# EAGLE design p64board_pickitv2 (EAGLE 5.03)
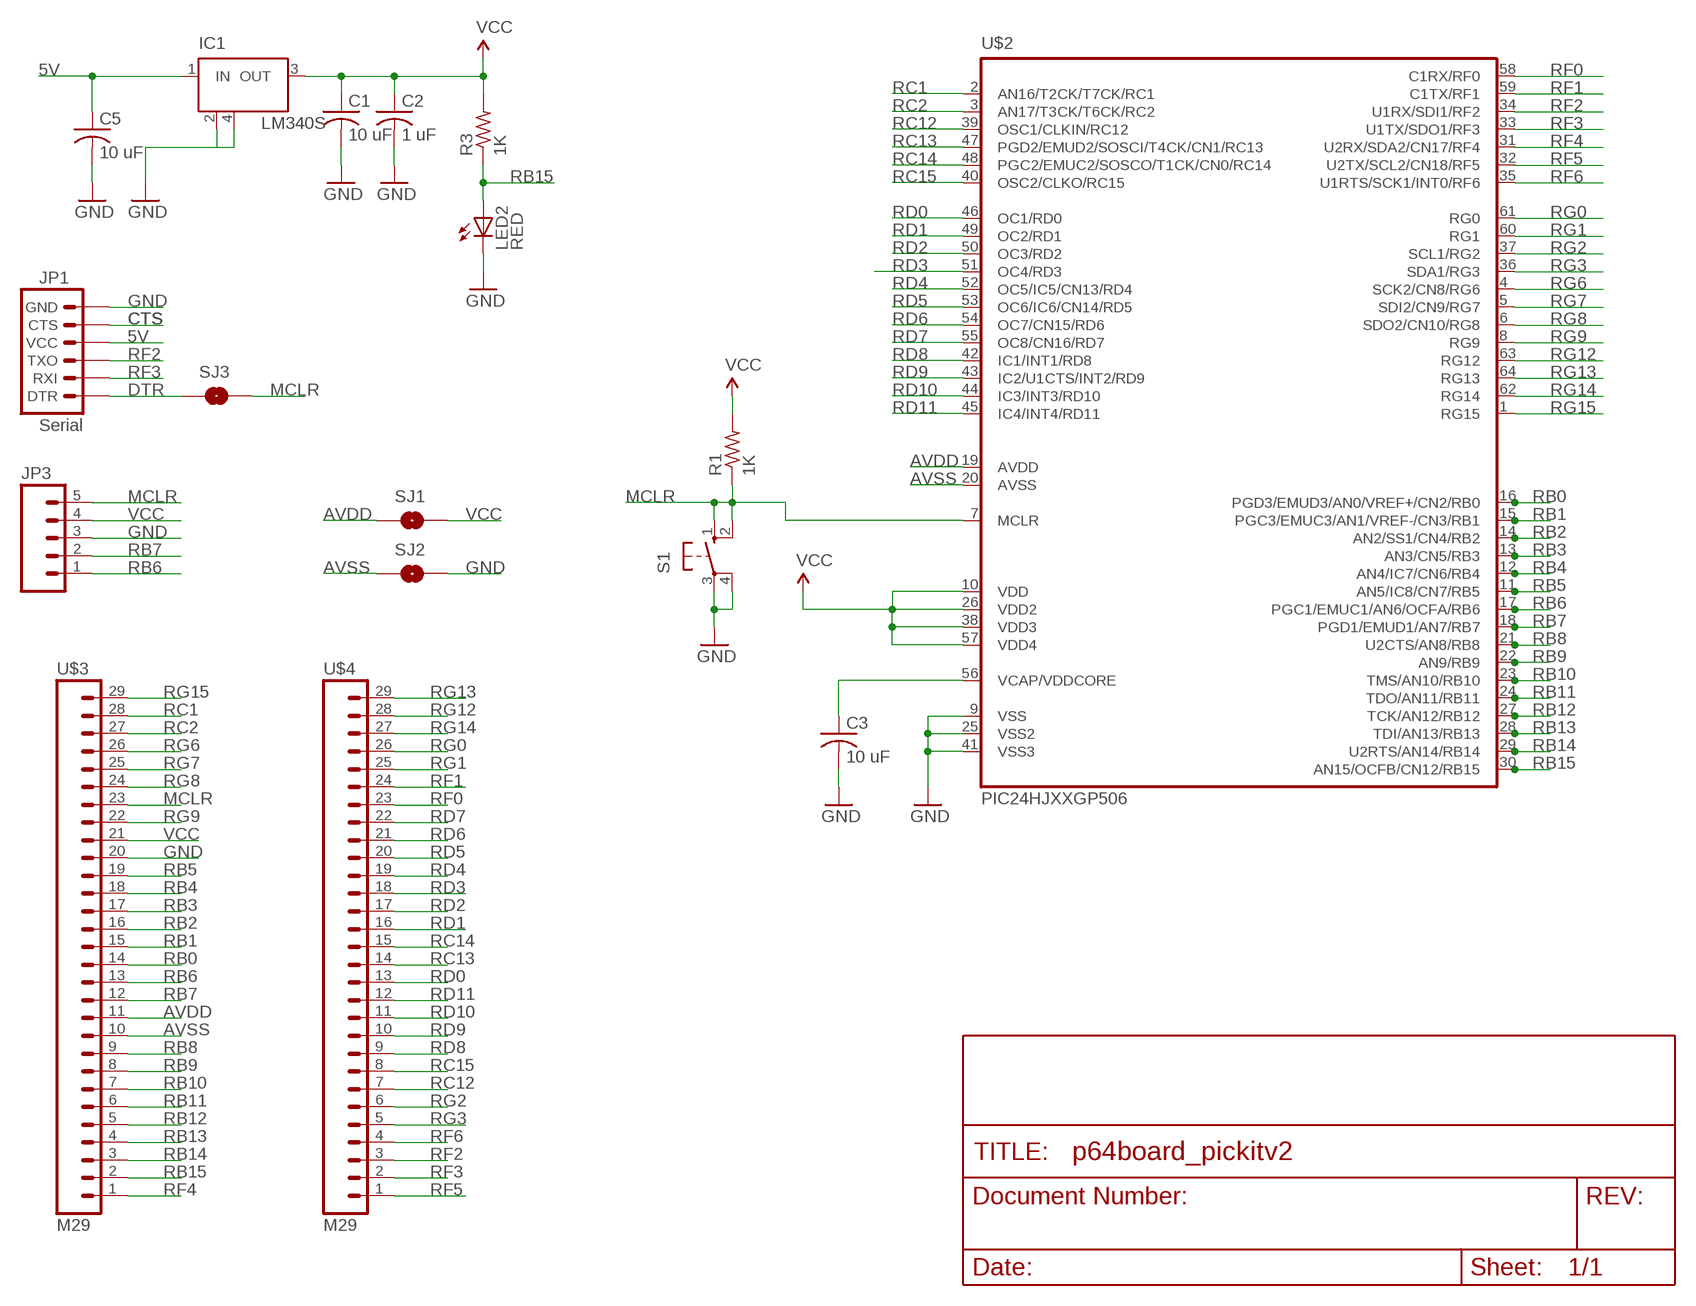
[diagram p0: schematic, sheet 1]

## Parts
C1  10 uF  C-US025-030X050  [C025-030X050]
C2  1 uF  C-US025-030X050  [C025-030X050]
C3  10 uF  C-US025-030X050  [C025-030X050]
C5  10 uF  C-US025-030X050  [C025-030X050]
IC1  LM340S  [SOT223]
JP1  Serial  ARDUINO_SERIAL_PROGRAMPTH  [1X06]
JP3  M05  [1X05]
LED2  RED  LED5MM  [LED5MM]
R1  1K  R-US_0204/7  [0204/7]
R3  1K  R-US_0204/7  [0204/7]
S1  10-XX  [B3F-10XX]
SJ1  Close  SOLDERJUMPERNC2  [SJ_2S]
SJ2  Close  SOLDERJUMPERNC2  [SJ_2S]
SJ3  Close  SOLDERJUMPERNC2  [SJ_2S]
U$2  PIC24HJXXGP506  [SQFP-S-10X10-64]
U$3  M29  [1X29]
U$4  M29  [1X29]

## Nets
5V: C5.1 IC1.1(IN) JP1.4(VCC)
AVDD: SJ1.1 U$3.11
AVSS: SJ2.1 U$3.10
CTS [vcc]: JP1.5(CTS)
DTR: JP1.1(DTR) SJ3.1
GND [vcc]: C1.2 C2.2 C3.2 C5.2 IC1.2(GND) IC1.4(GND) JP1.6(GND) JP3.3 LED2.K(C) S1.3(P) S1.4(P1) SJ2.2 U$2.9(VSS) U$2.25(VSS2) U$2.41(VSS3) U$3.20
MCLR: JP3.5 R1.1 S1.1(S) S1.2(S1) SJ3.2 U$2.7(MCLR) U$3.23
RB0: U$2.16(PGD3/EMUD3/AN0/VREF+/CN2/RB0) U$3.14
RB1: U$2.15(PGC3/EMUC3/AN1/VREF-/CN3/RB1) U$3.15
RB2: U$2.14(AN2/SS1/CN4/RB2) U$3.16
RB3: U$2.13(AN3/CN5/RB3) U$3.17
RB4: U$2.12(AN4/IC7/CN6/RB4) U$3.18
RB5: U$2.11(AN5/IC8/CN7/RB5) U$3.19
RB6: JP3.1 U$2.17(PGC1/EMUC1/AN6/OCFA/RB6) U$3.13
RB7: JP3.2 U$2.18(PGD1/EMUD1/AN7/RB7) U$3.12
RB8: U$2.21(U2CTS/AN8/RB8) U$3.9
RB9: U$2.22(AN9/RB9) U$3.8
RB10: U$2.23(TMS/AN10/RB10) U$3.7
RB11: U$2.24(TDO/AN11/RB11) U$3.6
RB12: U$2.27(TCK/AN12/RB12) U$3.5
RB13: U$2.28(TDI/AN13/RB13) U$3.4
RB14: U$2.29(U2RTS/AN14/RB14) U$3.3
RB15: LED2.A R3.1 U$2.30(AN15/OCFB/CN12/RB15) U$3.2
RC1: U$2.2(AN16/T2CK/T7CK/RC1) U$3.28
RC2: U$2.3(AN17/T3CK/T6CK/RC2) U$3.27
RC12: U$2.39(OSC1/CLKIN/RC12) U$4.7
RC13: U$2.47(PGD2/EMUD2/SOSCI/T4CK/CN1/RC13) U$4.14
RC14: U$2.48(PGC2/EMUC2/SOSCO/T1CK/CN0/RC14) U$4.15
RC15: U$2.40(OSC2/CLKO/RC15) U$4.8
RD0: U$2.46(OC1/RD0) U$4.13
RD1: U$2.49(OC2/RD1) U$4.16
RD2: U$2.50(OC3/RD2) U$4.17
RD3: U$2.51(OC4/RD3) U$4.18
RD4: U$2.52(OC5/IC5/CN13/RD4) U$4.19
RD5: U$2.53(OC6/IC6/CN14/RD5) U$4.20
RD6: U$2.54(OC7/CN15/RD6) U$4.21
RD7: U$2.55(OC8/CN16/RD7) U$4.22
RD8: U$2.42(IC1/INT1/RD8) U$4.9
RD9: U$2.43(IC2/U1CTS/INT2/RD9) U$4.10
RD10: U$2.44(IC3/INT3/RD10) U$4.11
RD11: U$2.45(IC4/INT4/RD11) U$4.12
RF0: U$2.58(C1RX/RF0) U$4.23
RF1: U$2.59(C1TX/RF1) U$4.24
RF2: JP1.3(TXO) U$2.34(U1RX/SDI1/RF2) U$4.3
RF3: JP1.2(RXI) U$2.33(U1TX/SDO1/RF3) U$4.2
RF4: U$2.31(U2RX/SDA2/CN17/RF4) U$3.1
RF5: U$2.32(U2TX/SCL2/CN18/RF5) U$4.1
RF6: U$2.35(U1RTS/SCK1/INT0/RF6) U$4.4
RG0: U$2.61(RG0) U$4.26
RG1: U$2.60(RG1) U$4.25
RG2: U$2.37(SCL1/RG2) U$4.6
RG3: U$2.36(SDA1/RG3) U$4.5
RG6: U$2.4(SCK2/CN8/RG6) U$3.26
RG7: U$2.5(SDI2/CN9/RG7) U$3.25
RG8: U$2.6(SDO2/CN10/RG8) U$3.24
RG9: U$2.8(RG9) U$3.22
RG12: U$2.63(RG12) U$4.28
RG13: U$2.64(RG13) U$4.29
RG14: U$2.62(RG14) U$4.27
RG15: U$2.1(RG15) U$3.29
VCAP: C3.1 U$2.56(VCAP/VDDCORE)
VCC: C1.1 C2.1 IC1.3(OUT) JP3.4 R1.2 R3.2 SJ1.2 U$2.10(VDD) U$2.26(VDD2) U$2.38(VDD3) U$2.57(VDD4) U$3.21

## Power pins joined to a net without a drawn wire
AVDD: U$2.19(AVDD)
AVSS: U$2.20(AVSS)

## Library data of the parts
C1-C3 C5 = rcl:C-US: CAPACITOR, American symbol
IC1 = linear:LM340S: 3-Terminal Positive Regulators Source: http://cache.national.com/ds/LM/LM340.pdf
JP1 = SparkFun:ARDUINO_SERIAL_PROGRAM
JP3 = SparkFun:M05: Header 5 Standard 5-pin 0.1" header. Use with straight break away headers (SKU : PRT-00116), right angle break away headers (PRT-00553), swiss pins (PRT-00743), machine pins (PRT-00117), and female headers (PRT-00115). Molex polarized connector foot print use with SKU : PRT-08230 with associated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
LED2 = led:LED: LED
R1 R3 = rcl:R-US_: RESISTOR, American symbol
S1 = switch-omron:10-XX: OMRON SWITCH
SJ1-SJ3 = SparkFun:SOLDERJUMPER: Solder Jumper
U$2 = SparkFun:PIC24HJXXGP506
U$3 U$4 = SparkFun:M29

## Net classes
0 default: width 0.203 mm
1 vcc: width 0.203 mm

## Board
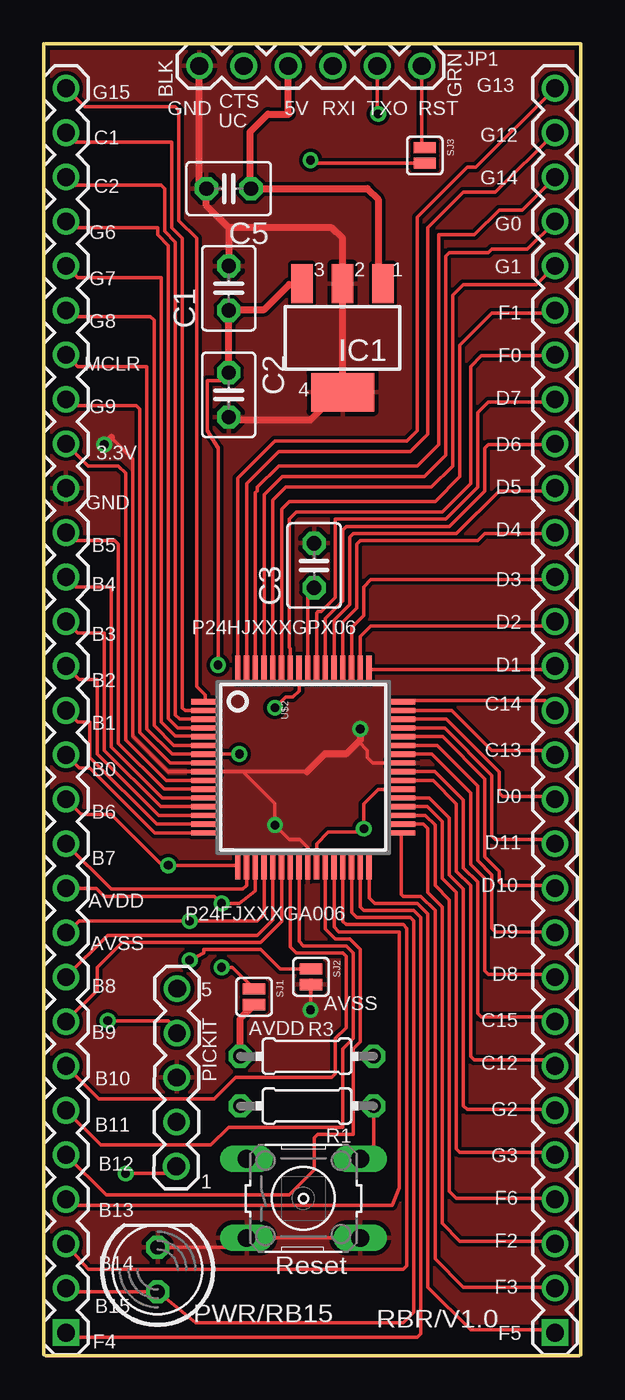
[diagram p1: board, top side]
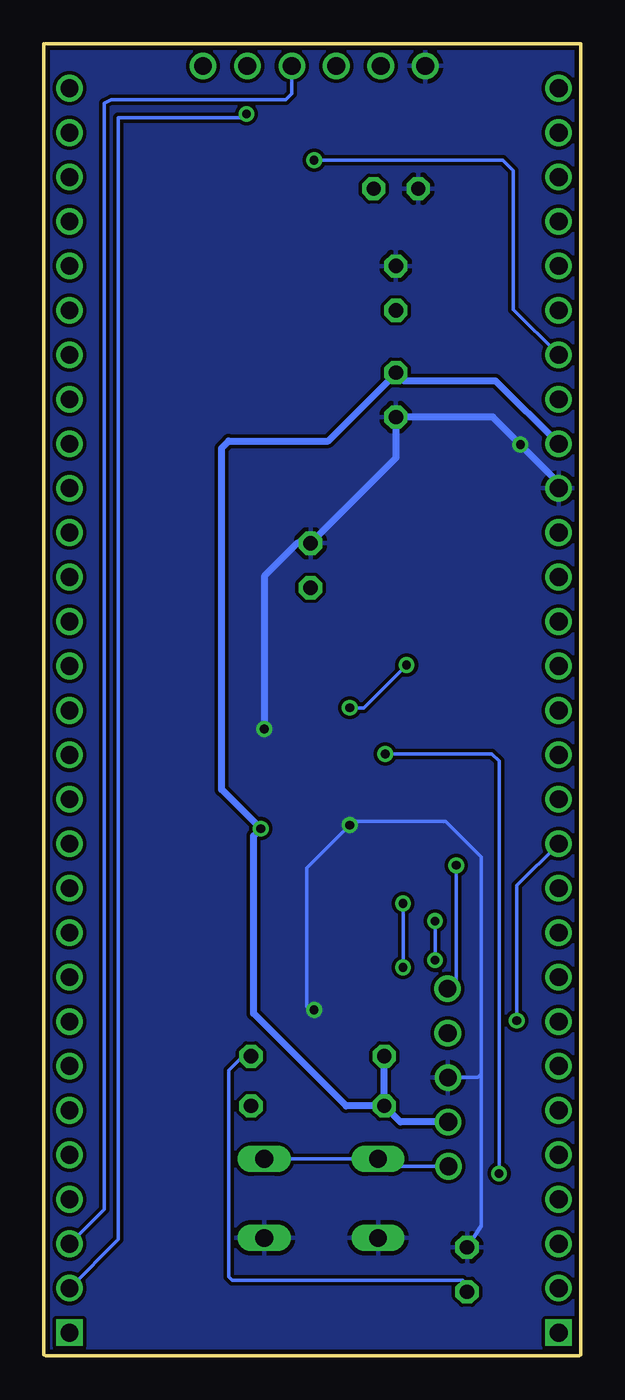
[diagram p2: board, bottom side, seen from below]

Size 30.68 x 74.98 mm. Coordinates in mm from the lower left corner, seen from the top.
Outline: 0.1,0 30.58,0
Outline: 0,74.98 0,0.05
Outline: 30.68,74.98 30.68,0.05
Outline: 0.1,74.98 30.58,74.98
Copper layers (1*16): Top 0.035mm / dielectric 1.5mm / Bottom 0.035mm
Design rules "default *": minimum track width 8mil, minimum drill 10mil, track to track 8mil, track to pad 8mil, pad to pad 7mil, via to via 8mil, smd to smd 8mil, copper to edge 10mil, drill to drill 8mil, minimum pad ring 10mil, minimum via ring 8mil, stop-mask expansion 4mil, vias tented up to drill 0mil, thermal gap 10mil

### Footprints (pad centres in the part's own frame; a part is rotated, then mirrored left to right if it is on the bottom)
C025-030X050 = drill 0.813 octagon: 1 -1.27,0; 2 1.27,0
SOT223 = smd 1.219 x 2.235: 1 -2.311,-3.099; 2 0,-3.099; 3 2.311,-3.099 | smd 3.6 x 2.2: 4 0,3.099
1X06 = drill 1.016 round: 1 0,0; 2 2.54,0; 3 5.08,0; 4 7.62,0; 5 10.16,0; 6 12.7,0
1X05 = drill 1.016 round: 1 0,0; 2 2.54,0; 3 5.08,0; 4 7.62,0; 5 10.16,0
LED5MM = drill 0.813 octagon: A -1.27,0; K 1.27,0
0204/7 = drill 0.813 octagon: 1 -3.81,0; 2 3.81,0
B3F-10XX = drill 1.016 long: 1 -3.251,2.261; 2 3.251,2.261; 3 -3.251,-2.261; 4 3.251,-2.261
SJ_2S = smd 0.635 x 1.27: 1 0,0; 2 0.889,0
SQFP-S-10X10-64 = smd 0.3 x 1.6: 1 -3.75,-5.6; 2 -3.25,-5.6; 3 -2.75,-5.6; 4 -2.25,-5.6; 5 -1.75,-5.6; 6 -1.25,-5.6; 7 -0.75,-5.6; 8 -0.25,-5.6; 9 0.25,-5.6; 10 0.75,-5.6; 11 1.25,-5.6; 12 1.75,-5.6; 13 2.25,-5.6; 14 2.75,-5.6; 15 3.25,-5.6; 16 3.75,-5.6; 33 3.75,5.6; 34 3.25,5.6; 35 2.75,5.6; 36 2.25,5.6; 37 1.75,5.6; 38 1.25,5.6; 39 0.75,5.6; 40 0.25,5.6; 41 -0.25,5.6; 42 -0.75,5.6; 43 -1.25,5.6; 44 -1.75,5.6; 45 -2.25,5.6; 46 -2.75,5.6; 47 -3.25,5.6; 48 -3.75,5.6 | smd 1.6 x 0.3: 17 5.6,-3.75; 18 5.6,-3.25; 19 5.6,-2.75; 20 5.6,-2.25; 21 5.6,-1.75; 22 5.6,-1.25; 23 5.6,-0.75; 24 5.6,-0.25; 25 5.6,0.25; 26 5.6,0.75; 27 5.6,1.25; 28 5.6,1.75; 29 5.6,2.25; 30 5.6,2.75; 31 5.6,3.25; 32 5.6,3.75; 49 -5.6,3.75; 50 -5.6,3.25; 51 -5.6,2.75; 52 -5.6,2.25; 53 -5.6,1.75; 54 -5.6,1.25; 55 -5.6,0.75; 56 -5.6,0.25; 57 -5.6,-0.25; 58 -5.6,-0.75; 59 -5.6,-1.25; 60 -5.6,-1.75; 61 -5.6,-2.25; 62 -5.6,-2.75; 63 -5.6,-3.25; 64 -5.6,-3.75
1X29 = drill 1.016 square: 1 0,0 | drill 1.016 round: 2 2.54,0; 3 5.08,0; 4 7.62,0; 5 10.16,0; 6 12.7,0; 7 15.24,0; 8 17.78,0; 9 20.32,0; 10 22.86,0; 11 25.4,0; 12 27.94,0; 13 30.48,0; 14 33.02,0; 15 35.56,0; 16 38.1,0; 17 40.64,0; 18 43.18,0; 19 45.72,0; 20 48.26,0; 21 50.8,0; 22 53.34,0; 23 55.88,0; 24 58.42,0; 25 60.96,0; 26 63.5,0; 27 66.04,0; 28 68.58,0; 29 71.12,0

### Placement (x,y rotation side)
C1  10.57,61.01 90 top
C2  10.57,54.91 270 top
C3  15.44,45.16 90 top
C5  10.57,66.7 180 top
IC1  17.07,58.17 180 top
JP1  21.59,73.71 180 top
JP3  7.62,20.98 269.7 top
LED2  6.5,4.93 90 top
R1  15.04,14.27 180 top
R3  15.04,17.12 180 top
S1  14.83,8.99 0 top
SJ1  12.01,20.95 270 top
SJ2  15.27,22.1 270 top
SJ3  21.77,69.04 270 top
U$2  14.83,33.63 270 top
U$3  1.27,1.32 90 top
U$4  29.21,1.32 90 top

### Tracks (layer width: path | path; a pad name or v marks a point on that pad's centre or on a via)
5V
  Top 0.406: JP1.4 13.97,71.02 14.02,70.97 12.8,70.97 11.79,69.95 11.79,66.75 C5.1 18.49,66.7 19.1,66.09 19.1,61.54 IC1.1
AVDD  (via drill 0.5)
  Top 0.203: U$2.19 12.08,26.56 11.18,25.86 v10.16,25.86 9.75,26.26 3.45,26.26 3,26.72 U$3.11 | v10.16,22.2 10.77,22.2 SJ1.1
  Bottom 0.203: v10.16,25.86 v10.16,22.2
AVSS  (via drill 0.5)
  Top 0.203: U$2.20 12.58,25.23 12.19,24.84 v8.33,24.84 2.03,24.84 1.37,24.18 U$3.10 | SJ2.1 13.51,22.1 12.39,23.22 9.14,23.22 9.14,23.01 v8.33,22.61
  Bottom 0.203: 8.33,24.43 v8.33,24.84 v8.33,22.61
DTR
  Top 0.203: JP1.1 21.59,69.21 SJ3.1
GND  (via drill 0.5)
  Top 0.203: 7.12,33.38 U$2.9 | 7.12,33.38 7.11,33.38 5.08,35.41 5.08,51.26 3.86,52.48 | U$2.41 18.8,33.88 18.49,34.19 18.49,34.59 17.98,35.1 | U$2.25 15.08,29.06 14.63,29.51 14.02,29.51 v13.21,30.33 13.21,31.55 11.38,33.38 | S1.3 11.46,6.6 | S1.3 S1.4 | 11.38,33.38 7.12,33.38 | 11.38,33.38 15.04,33.38 | SJ2.2 15.27,19.79 v15.24,19.76 | LED2.K 11.05,6.2 S1.3
  Top 0.406: JP1.6 8.89,67.11 C5.2 9.3,65.73 10.57,64.46 | 10.57,64.46 C1.2 | 10.57,64.46 16.46,64.46 17.07,63.86 IC1.2 IC1.4 16.82,55.07 15.24,53.49 10.72,53.49 C2.2 | 3.86,52.48 v3.45,52.07 | v18.09,35.81 18.09,35.2 17.98,35.1 17.27,34.39 16.1,34.39 | 15.04,33.38 16.05,34.39
  Bottom 0.203: v15.24,19.76 15.44,19.76 15.65,19.96 15.65,27.89 v13.21,30.33 13.01,30.53 7.72,30.53 5.69,28.5 5.69,16.1 | 5.69,16.1 5.69,7.42 LED2.K | JP3.3 5.89,15.9 5.69,16.1
  Bottom 0.406: U$3.20 1.27,49.89 v3.45,52.07 5.03,53.64 C2.2 10.57,51.31 C3.2 16.2,46.43 18.09,44.55 v18.09,35.81
  pour Top: 0,0.05 0,74.83 30.68,74.83 30.68,0.05
  pour Bottom: 0,0.05 0,74.83 30.68,74.83 30.68,0.05
MCLR  (via drill 0.5)
  Top 0.203: U$3.23 1.93,56.54 5.89,56.54 5.89,35.81 7.33,34.38 U$2.7 11.16,34.38 v11.18,34.39 | R1.1 18.85,12.01 S1.2 | SJ3.2 15.42,68.15 v15.24,68.33 | v4.67,10.41 7.16,10.41 JP3.5
  Bottom 0.203: v4.67,10.41 4.67,33.98 5.08,34.39 v11.18,34.39 | v15.24,68.33 4.47,68.33 3.86,67.72 3.86,59.79 U$3.23 | JP3.5 11.15,10.82 S1.1 S1.2
RB0
  Top 0.203: U$2.16 6.34,29.88 2.64,33.58 2.03,33.58 U$3.14
RB1
  Top 0.203: U$2.15 6.45,30.38 2.64,34.19 2.64,36.22 1.93,36.22 U$3.15
RB2
  Top 0.203: U$2.14 6.56,30.88 3.05,34.39 3.05,38.66 2.03,38.66 U$3.16
RB3
  Top 0.203: U$2.13 6.67,31.38 3.45,34.59 3.45,41.3 1.93,41.3 U$3.17
RB4
  Top 0.203: U$2.12 6.78,31.88 3.86,34.8 3.86,43.94 1.83,43.94 U$3.18
RB5
  Top 0.203: U$2.11 6.89,32.38 4.27,35 4.27,46.38 4.06,46.58 1.73,46.58 U$3.19
RB6  (via drill 0.5)
  Top 0.203: U$3.13 2.13,30.94 3.86,30.94 6.77,28.03 v7.11,28.03 U$2.17
  Bottom 0.203: v7.11,28.03 7.11,21.49 JP3.1
RB7  (via drill 0.5)
  Top 0.203: U$2.18 11.58,26.87 11.38,26.67 3.86,26.67 U$3.12 | JP3.2 7.61,18.66 7.11,19.15 v3.66,19.15
  Bottom 0.203: v3.66,19.15 3.66,26.87 U$3.12
RB8
  Top 0.203: U$2.21 13.08,24.92 12.19,24.03 3.66,24.03 U$3.9
RB9
  Top 0.203: U$2.22 13.58,24.81 12.39,23.62 4.47,23.62 3.05,22.2 3.05,20.88 U$3.8
RB10
  Top 0.203: U$2.23 14.08,23.36 14.43,23.01 17.07,23.01 17.27,22.81 17.27,18.74 16.66,18.14 16.66,16.1 16.46,15.9 10.97,15.9 9.75,14.68 3.15,14.68 U$3.7
RB11
  Top 0.203: U$2.24 14.58,23.67 14.83,23.42 17.27,23.42 17.68,23.01 17.68,18.14 17.07,17.53 17.07,13.06 10.57,13.06 9.55,12.04 3.25,12.04 U$3.6
RB12
  Top 0.203: U$2.27 16.08,24.4 16.66,23.82 17.48,23.82 18.09,23.22 18.09,17.93 17.68,17.53 17.68,12.65 15.65,12.65 15.44,12.45 15.44,10.62 14.02,9.19 3.56,9.19 U$3.5
RB13
  Top 0.203: U$2.28 16.58,24.51 16.87,24.23 20.32,24.23 20.32,9.6 19.91,8.58 1.52,8.58 U$3.4
RB14
  Top 0.203: U$2.29 17.08,24.83 17.27,24.64 20.52,24.64 20.73,24.43 20.73,5.13 20.52,4.93 2.54,4.93 U$3.3
RB15
  Top 0.203: U$2.30 17.58,25.34 17.88,25.04 20.93,25.04 21.13,24.84 21.13,2.49 20.52,1.88 8.69,1.88 LED2.A 1.47,3.66 U$3.2
  Bottom 0.203: R3.1 19.3,17.12 20.12,16.31 20.12,4.52 19.91,4.32 6.76,4.32 LED2.A
RC1
  Top 0.203: U$2.2 9.24,36.88 9.25,36.88 8.08,36.88 7.92,37.03 7.92,63.86 7.32,64.46 7.32,69.34 1.83,69.34 U$3.28
RC2
  Top 0.203: U$2.3 7.77,36.38 7.52,36.63 7.52,63.65 6.91,64.26 6.91,66.7 6.71,66.9 1.73,66.9 U$3.27
RC12
  Top 0.203: U$2.39 22.24,32.88 23.57,31.55 23.57,27.69 24.38,26.87 24.38,17.12 24.59,16.92 28.85,16.92 U$4.7
RC13
  Top 0.203: U$2.47 23.32,36.88 25.6,34.59 28.96,34.59 U$4.14
RC14
  Top 0.203: U$2.48 20.46,37.38 20.52,37.44 28.65,37.44 U$4.15
RC15
  Top 0.203: U$2.40 22.35,33.38 23.98,31.75 23.98,27.89 24.79,27.08 24.79,19.56 24.99,19.35 28.96,19.35 U$4.8
RD0
  Top 0.203: U$2.46 23.01,36.38 26.01,33.38 26.01,32.16 26.21,31.95 29.06,31.95 U$4.13
RD1
  Top 0.203: U$2.49 29.02,39.23 U$4.16
RD2
  Top 0.203: U$2.50 18.08,41.1 18.69,41.71 28.96,41.71 U$4.17
RD3
  Top 0.203: U$2.51 17.58,41.61 18.29,42.32 18.29,43.94 18.69,44.35 29.06,44.35 U$4.18
RD4
  Top 0.203: U$2.52 17.08,41.92 17.88,42.72 17.88,46.38 18.09,46.58 24.79,46.58 25.2,46.99 29.16,46.99 U$4.19
RD5
  Top 0.203: U$2.53 16.58,42.03 17.48,42.93 17.48,46.79 17.68,46.99 23.57,46.99 26.01,49.43 29.06,49.43 U$4.20
RD6
  Top 0.203: U$2.54 16.08,42.14 17.07,43.13 17.07,47.19 17.27,47.4 23.16,47.4 25.2,49.43 25.2,51.87 25.4,52.07 29.16,52.07 U$4.21
RD7
  Top 0.203: U$2.55 15.58,42.46 15.65,42.52 15.85,42.52 16.66,43.33 16.66,47.8 22.96,47.8 24.79,49.63 24.79,53.9 25.4,54.51 29.06,54.51 U$4.22
RD8
  Top 0.203: U$2.42 22.16,34.38 24.38,32.16 24.38,28.09 25.2,27.28 25.2,22 25.4,21.79 29.06,21.79 U$4.9
RD9
  Top 0.203: U$2.43 22.47,34.88 24.79,32.56 24.79,28.3 25.6,27.48 25.6,24.43 25.81,24.23 29.16,24.23 U$4.10
RD10
  Top 0.203: U$2.44 22.79,35.38 25.2,32.97 25.2,28.5 26.01,27.69 26.01,27.08 26.21,26.87 29.06,26.87 U$4.11
RD11
  Top 0.203: U$2.45 22.9,35.88 25.6,33.17 25.6,29.72 25.81,29.51 28.96,29.51 U$4.12
RF0
  Top 0.203: U$2.58 14.08,40.42 14.02,40.49 14.02,47.8 14.43,48.21 22.76,48.21 24.38,49.83 24.38,56.54 24.99,57.15 29.16,57.15 U$4.23
RF1
  Top 0.203: U$2.59 13.58,48.38 14.02,48.82 22.35,48.82 23.77,50.24 23.77,57.76 25.6,59.59 29.06,59.59 U$4.24
RF2
  Top 0.203: U$2.34 21.46,30.38 21.69,30.38 21.95,30.12 21.95,26.47 22.76,25.65 22.76,7.57 23.77,6.55 29.06,6.55 U$4.3
  Bottom 0.203: JP1.3 16.51,72.14 16.87,71.78 26.82,71.78 27.23,71.58 27.23,8.38 U$4.3
RF3  (via drill 0.5)
  Top 0.203: U$2.33 20.43,26.35 20.52,26.26 21.54,26.26 22.35,25.45 22.35,5.54 23.98,3.91 29.16,3.91 U$4.2 | JP1.2 19.05,71.02 v19.1,70.97
  Bottom 0.203: v19.1,70.97 19.3,70.76 26.42,70.76 26.42,6.65 U$4.2
RF4
  Top 0.203: U$2.31 18.08,25.65 18.29,25.45 21.13,25.45 21.54,25.04 21.54,1.27 21.34,1.07 1.52,1.07 U$3.1
RF5
  Top 0.203: U$2.32 18.58,26.17 18.9,25.86 21.34,25.86 21.95,25.25 21.95,3.91 24.38,1.47 29.06,1.47 U$4.1
RF6
  Top 0.203: U$2.35 21.8,30.88 22.35,30.33 22.35,26.87 23.16,26.06 23.16,9.4 23.57,8.99 29.16,8.99 U$4.4
RG0
  Top 0.203: U$2.61 12.58,49.21 13.61,50.24 21.74,50.24 22.96,51.46 22.96,62.84 23.16,63.04 25.4,63.04 25.6,63.25 27.64,63.25 U$4.26
RG1
  Top 0.203: U$2.60 13.08,48.9 13.82,49.63 22.15,49.63 23.37,50.85 23.37,60.6 23.98,61.21 28.14,61.21 U$4.25
RG2
  Top 0.203: U$2.37 22.02,31.88 23.16,30.73 23.16,27.48 23.98,26.67 23.98,14.27 24.18,14.07 29.16,14.07 U$4.6
RG3
  Top 0.203: U$2.36 21.91,31.38 22.76,30.53 22.76,27.28 23.57,26.47 23.57,11.84 23.77,11.63 29.06,11.63 U$4.5
RG6
  Top 0.203: U$2.4 7.66,35.88 7.11,36.42 7.11,63.45 6.5,64.06 6.5,64.46 1.63,64.46 U$3.26
RG7
  Top 0.203: U$2.5 9.32,35.38 9.35,35.41 7.52,35.41 6.71,36.22 6.71,61.62 1.93,61.62 U$3.25
RG8
  Top 0.203: U$2.6 7.44,34.88 6.3,36.02 6.3,59.18 6.1,59.38 1.63,59.38 U$3.24
RG9
  Top 0.203: U$2.8 7.22,33.88 5.49,35.61 5.49,54.1 5.28,54.3 1.63,54.3 U$3.22
RG12
  Top 0.203: U$2.63 11.58,49.84 13.41,51.66 20.93,51.66 21.95,52.68 21.95,64.46 23.98,66.5 25.81,66.5 U$4.28
RG13
  Top 0.203: U$2.64 11.08,50.15 13.21,52.27 20.73,52.27 21.34,52.88 21.34,65.07 24.18,67.92 24.69,67.92 U$4.29
RG14
  Top 0.203: U$2.62 12.08,49.32 12.19,49.43 12.19,49.63 13.41,50.85 21.34,50.85 22.55,52.07 22.55,64.06 24.59,64.06 26.01,65.48 27.33,65.48 U$4.27
RG15
  Top 0.203: U$2.1 9.23,37.76 8.74,38.25 8.74,63.86 7.72,64.87 7.72,71.17 7.52,71.37 2.34,71.37 U$3.29
VCAP
  Top 0.203: U$2.56 15.08,43.53 C3.1
VCC  (via drill 0.5)
  Top 0.203: U$2.57 14.58,38 14.22,37.64 13.82,37.64 v13.21,37.03 | v9.96,39.47 9.96,51.87 9.35,52.88 9.35,55.73 10.11,55.73 C2.1 | U$2.10 7,32.88 4.67,35.2 4.67,50.44 4.27,50.85 2.54,50.85 U$3.21 | U$2.26 15.58,29.25 16.26,29.92 18.09,29.92 v18.29,30.12 18.29,31.55 18.39,31.65 19.1,32.36 20.41,32.36 U$2.38
  Top 0.406: IC1.3 14.78,61.26 14.83,61.21 14.02,61.21 12.6,59.79 10.62,59.79 C1.1 C2.1 | R3.2 11.23,19.28 SJ1.2
  Bottom 0.203: v13.21,37.03 12.39,37.03 v9.96,39.47
  Bottom 0.406: U$3.21 4.88,55.73 10.11,55.73 C2.1 10.57,56.13 14.43,52.27 20.12,52.27 20.52,51.87 20.52,32.36 v18.29,30.12 18.69,29.72 18.69,19.56 13.41,14.27 R1.2 | R1.2 R3.2 | JP3.4 10.31,13.36 R1.2

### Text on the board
tPlace: G15 | G13 | BLK | GRN | GND | CTS | UC | 5V | RXI | TXO | RST | C1 | G12 | G14 | C2 | G6 | G0 | G1 | G7 | F1 | G8 | F0 | MCLR | G9 | D7 | 3.3V | D6 | D5 | GND | D4 | B5 | D3 | B4 | B3 | P24HJXXXGPX06 | D2 | D1 | B2 | C14 | B1 | C13 | B0 | D0 | B6 | D11 | B7 | D10 | AVDD | P24FJXXXGA006 | D9 | AVSS | D8 | B8 | 5 | AVSS | C15 | B9 | AVDD | C12 | B10 | PICKIT | B11 | G2 | G3 | B12 | 1 | B13 | F6 | F2 | B14 | Reset | F3 | B15 | PWR/RB15 | RBR/V1.0 | F5 | F4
